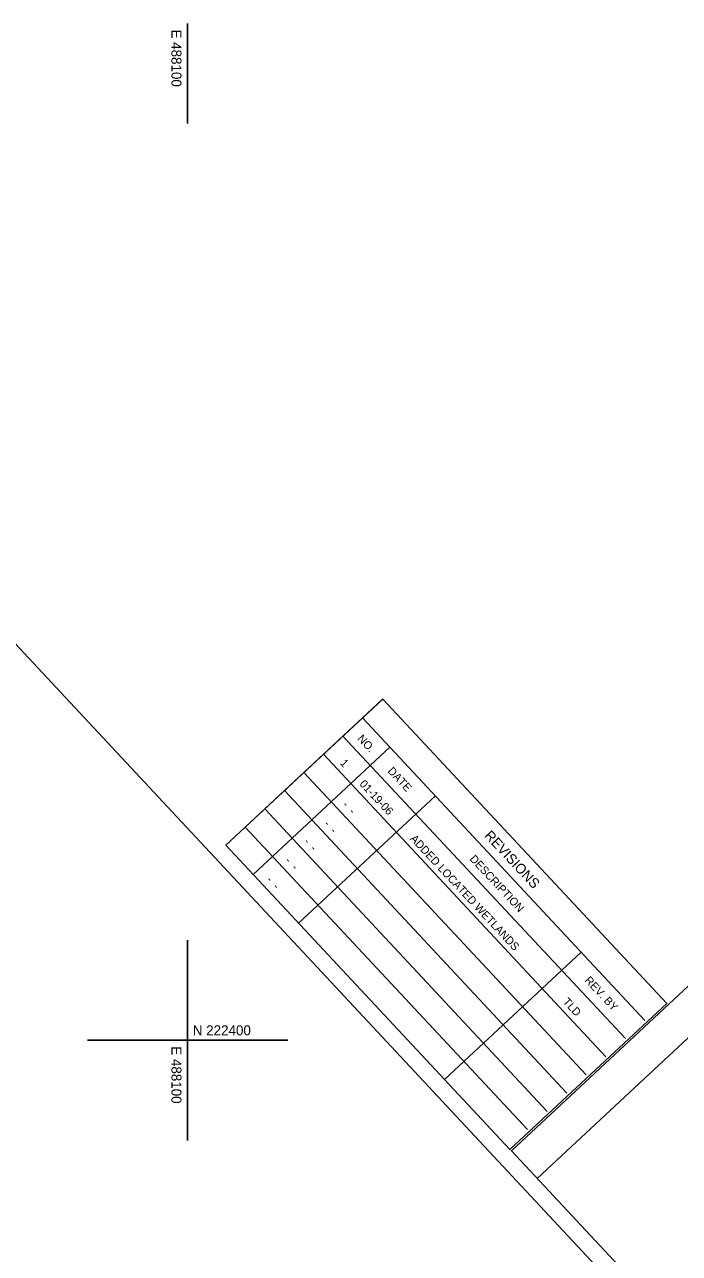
# Model space of a CAD drawing. Extents: x 487096 to 489566, y 221939 to 224454.
# Drawn here: x 488035.9 to 488293.4, y 222316.2 to 222799.6 of the extents above; entities that cross this region are included whole.
import ezdxf

# ---------------------------------------------------------------- set-up
doc = ezdxf.new("R2010")
doc.units = 0
for name, color, linetype in [('SV_GRID_GRID', 7, 'Continuous'), ('SV_MAPI_BORDERS', 7, 'Continuous'), ('SV_MAPI_NOTE', 7, 'Continuous')]:
    doc.layers.add(name, color=color, linetype=linetype)

msp = doc.modelspace()

# ---------------------------------------------------------------- linework, layer by layer
at = {"layer": 'SV_GRID_GRID'}
for p, q in [((488100, 222800), (488100, 222760.63)), ((488100, 222400), (488100, 222439.37)), ((488060.63, 222400), (488100, 222400)), ((488100, 222400), (488139.37, 222400)), ((488100, 222400), (488100, 222360.63))]:
    msp.add_line(p, q, dxfattribs=at)
at = {"layer": 'SV_MAPI_BORDERS'}
msp.add_line((488442.2, 222536.65), (488237.42, 222345.69), dxfattribs=at)
for points in [[(488607.95, 221938.76), (487095.64, 223560.51), (488053.67, 224453.88), (489565.97, 222832.14)], [(488609.23, 221946.97), (488227.31, 222356.53), (488432.09, 222547.49), (488814.01, 222137.93)]]:
    msp.add_lwpolyline(points, close=True, dxfattribs=at)
at = {"layer": 'SV_MAPI_NOTE'}
for p, q in [((488176.45, 222534.03), (488115.02, 222476.74)), ((488279.77, 222407.84), (488168.77, 222526.87)), ((488272.1, 222400.67), (488161.09, 222519.71)), ((488179.52, 222515.35), (488125.76, 222465.22)), ((488264.42, 222393.51), (488153.42, 222512.55)), ((488256.74, 222386.35), (488145.74, 222505.39)), ((488249.06, 222379.19), (488138.06, 222498.22)), ((488197.42, 222496.15), (488143.66, 222446.02)), ((488241.38, 222372.02), (488130.38, 222491.07)), ((488233.7, 222364.86), (488122.69, 222483.9)), ((488115.02, 222476.74), (488226.7, 222356.98)), ((488254.71, 222434.71), (488200.95, 222384.58)), ((488226.7, 222356.98), (488288.38, 222414.51))]:
    msp.add_line(p, q, dxfattribs=at)
msp.add_lwpolyline([(488115.02, 222476.74), (488226.7, 222356.98), (488288.38, 222414.51), (488176.71, 222534.27)], close=True, dxfattribs=at)

# ---------------------------------------------------------------- texts
at = {"layer": 'SV_GRID_GRID'}
for p in [(488093.66, 222797.64), (488093.66, 222397.64)]:
    msp.add_text('E 488100', height=3.937, rotation=270, dxfattribs=at).set_placement(p)
msp.add_text('N 222400', height=3.937, dxfattribs=at).set_placement((488102.05, 222401.96))
at = {"layer": 'SV_MAPI_NOTE'}
for s, height, p in [('NO.', 3.15, (488166.55, 222518.48)), (' 1', 3.15, (488158.94, 222509.71)), ('DATE', 3.15, (488178.43, 222505.74)), ('01-19-06', 3.15, (488167.38, 222500.65)), ('  -  -  ', 3.15, (488159.1, 222494.14)), ('  -  -  ', 3.15, (488151.78, 222486.58)), ('  -  -  ', 3.15, (488143.92, 222479.62)), ('  ADDED LOCATED WETLANDS ', 3.1496, (488185.67, 222480.84)), ('REVISIONS', 3.937, (488216.42, 222480.3)), ('DESCRIPTION', 3.1502, (488210.68, 222471.15)), ('  -  -  ', 3.15, (488136.51, 222472.16)), ('  -  -  ', 3.15, (488129.2, 222464.6)), ('REV. BY', 3.15, (488255.89, 222423.39)), ('  TLD  ', 3.15, (488245.71, 222416.65))]:
    msp.add_text(s, height=height, rotation=313, dxfattribs=at).set_placement(p)

doc.saveas('drawing.dxf')
